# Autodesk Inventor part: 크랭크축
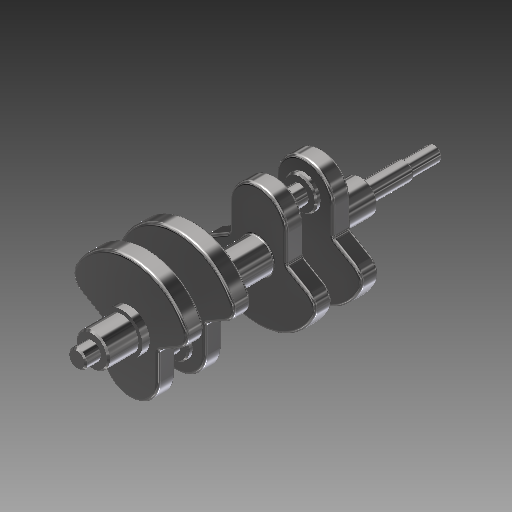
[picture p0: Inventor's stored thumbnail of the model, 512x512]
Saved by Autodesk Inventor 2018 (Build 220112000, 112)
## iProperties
Created: 2017-03
Part Number: 크랭크축
Material: 강철, 탄소
Document SubType Name: Modeling
Designer: mduedu
Density: 7.87 g/cm^3
Mass: 1840.77 g
Surface Area: 500.249 cm^2
Volume: 233.897 cm^3
Appearance: 반광택
Author: mduedu
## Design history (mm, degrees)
sketch "스케치1" dims "d5" = 57
  geometry: L1 (-19, 21.243)-(-19, 3.243); L2 (-19, 3.243)-(-40.023, -8.895); L3 (19, 21.243)-(19, 3.243); L4 (0, 21.243)-(0, -41); L5 (19, 3.243)-(40.023, -8.895); C1 r 6 at (0, 0); C2 r 13.5 at (0, 0); A1 r 41 centre (0, 0) between (-40.023, -8.895) and (0, -41); A2 r 41 centre (0, 0) between (0, -41) and (40.023, -8.895); A3 r 19 centre (0, 21.243) between (19, 21.243) and (0, 40.243); A4 r 19 centre (0, 21.243) between (0, 40.243) and (-19, 21.243); 3 further points
  constraints: 10 end point, 8 point on circle, 6 centre point, 5 coincident, 3 symmetric about line, 2 point on line, 1 parallel, 1 tangent, 1 vertical, 1 vertical alignment, 5 other
  dimensions: "d0" = 12 diameter of C1; "d1" = 27 diameter of C2; "d2" = 18 distance of L1.start L1.end; "d3" = 120 deg angle of L2 L1; "d4" = 41 radius of A1; "d6" = 19 radius of A4
extrude "돌출1" new body sketch "스케치1" distance "d7" = 12; taper "d8" = 0 deg
extrude "돌출2" join sketch "스케치1" distance "d9" = 5; taper "d10" = 0 deg
extrude "돌출3" join sketch "스케치1" distance "d11" = 75; taper "d12" = 0 deg
sketch "스케치2"
  geometry: C1 r 11 at (0, 21.243); C2 r 6 at (0, 21.243); A1 r 19 centre (0, 21.243) between (19, 21.243) and (-19, 21.243) reference; 1 further point
  constraints: 2 centre point, 2 coincident
  dimensions: "d13" = 22 diameter of C1; "d14" = 12 diameter of C2
extrude "돌출4" join sketch "스케치2" distance "d15" = 3; taper "d16" = 0 deg
extrude "돌출5" join sketch "스케치2" distance "d17" = 16; taper "d18" = 0 deg
fillet "모깎기1" dims "d19" = 3, "d20" = 10
fillet "모깎기2" dims "d21" = 2
sketch "스케치3"
  geometry: C1 r 11 at (0, 0); 1 further point
  constraints: 1 centre point, 1 coincident
  dimensions: "d22" = 22 diameter of C1
extrude "돌출6" join sketch "스케치3" distance "d23" = 21; taper "d24" = 0 deg
sketch "스케치4"
  geometry: C1 r 6 at (0, 0) reference; C2 r 5 at (0, 0); 1 further point
  constraints: 1 centre point
  dimensions: "d25" = 1 radial gap between concentric circles of C1 C2
extrude "돌출7" cut sketch "스케치4" distance "d26" = 20; taper "d27" = 0 deg
node "작업 평면1"
sketch "스케치5"
  geometry: L1 (-5, 0)-(5, 0) reference; L2 (-1.5, 0)-(1.5, 0); L3 (1.5, 0)-(1.5, 8.5); L4 (-1.5, 8.5)-(-1.5, 0); A1 r 1.5 centre (0, 8.5) between (1.5, 8.5) and (-1.5, 8.5); 1 further point
  constraints: 6 end point, 2 point on circle, 2 tangent, 1 centre point, 1 horizontal, 1 parallel, 1 perpendicular, 1 point on line, 1 vertical alignment
  dimensions: "d28" = 3 distance between parallel lines of L3 L4; "d30" = 10 dimension on A1 L1
extrude "돌출8" cut sketch "스케치5" distance "d31" = 1.8; taper "d32" = 0 deg
chamfer "모따기1" distance "d33" = 1; stored, may be unused: second distance "d34" = 2, angle "d35" = 45 deg
chamfer "모따기2" distance "d36" = 1; stored, may be unused: second distance "d37" = 2, angle "d38" = 45 deg
node "작업 평면2"
sketch "스케치6"
  geometry: C1 r 11 at (0, 0) reference; C2 r 11 at (0, 0) reference; 1 further point
extrude "돌출9" join sketch "스케치6" distance "d39" = 42; taper "d40" = 0 deg
sketch "스케치7" dims "d46" = 57
  geometry: L1 (-19, -21.243)-(-19, -3.243); L2 (19, -21.243)-(19, -3.243); L3 (-19, -3.243)-(-40.023, 8.895); L4 (19, -3.243)-(40.023, 8.895); L5 (0, -21.243)-(0, 41); C1 r 13.5 at (0, 0); C2 r 6 at (0, 0); A1 r 19 centre (0, -21.243) between (0, -40.243) and (19, -21.243); A2 r 19 centre (0, -21.243) between (-19, -21.243) and (0, -40.243); A3 r 41 centre (0, 0) between (0, 41) and (-40.023, 8.895); A4 r 41 centre (0, 0) between (40.023, 8.895) and (0, 41); 3 further points
  constraints: 10 end point, 8 point on circle, 6 centre point, 5 coincident, 3 symmetric about line, 2 point on line, 1 parallel, 1 tangent, 1 vertical, 5 other
  dimensions: "d41" = 12 diameter of C2; "d42" = 27 diameter of C1; "d43" = 18 distance of L2.start L2.end; "d44" = 120 deg angle of L4 L2; "d45" = 41 radius of A4; "d47" = 19 radius of A1
extrude "돌출10" join sketch "스케치7" distance "d48" = 12; taper "d49" = 0 deg
sketch "스케치8"
  geometry: C1 r 11 at (0, -21.243); C2 r 6 at (0, -21.243); A1 r 19 centre (0, -21.243) between (-19, -21.243) and (19, -21.243) reference; 1 further point
  constraints: 2 centre point, 2 coincident
  dimensions: "d50" = 22 diameter of C1; "d51" = 12 diameter of C2
extrude "돌출11" join sketch "스케치8" distance "d52" = 3; taper "d53" = 0 deg
extrude "돌출12" join sketch "스케치8" distance "d54" = 16; taper "d55" = 0 deg
fillet "모깎기3" dims "d56" = 3, "d57" = 10
fillet "모깎기4" dims "d58" = 2
chamfer "모따기3" distance "d59" = 1; stored, may be unused: second distance "d60" = 2, angle "d61" = 45 deg
node "작업 평면3"
fillet "모깎기5" dims "d62" = 1
sketch "스케치9"
  geometry: C1 r 13.5 at (0, 0) reference; 1 further point
extrude "돌출13" join sketch "스케치9" distance "d63" = 5; taper "d64" = 0 deg
sketch "스케치10"
  geometry: C1 r 6 at (0, 0) reference; 1 further point
extrude "돌출14" join sketch "스케치10" distance "d65" = 30; taper "d66" = 0 deg
sketch "스케치11"
  geometry: C1 r 11 at (0, 0); 1 further point
  constraints: 1 centre point, 1 coincident
  dimensions: "d67" = 22 diameter of C1
extrude "돌출15" join sketch "스케치11" distance "d68" = 20; taper "d69" = 0 deg
chamfer "모따기4" distance "d70" = 1; stored, may be unused: second distance "d71" = 2, angle "d72" = 45 deg
chamfer "모따기5" distance "d75" = 0.7; stored, may be unused: second distance "d76" = 2, angle "d77" = 30 deg
fillet "모깎기6" dims "d78" = 0.3
node "솔리드1"
mirror "대칭1"
mirror "대칭2"
node "투영된 루프1"
